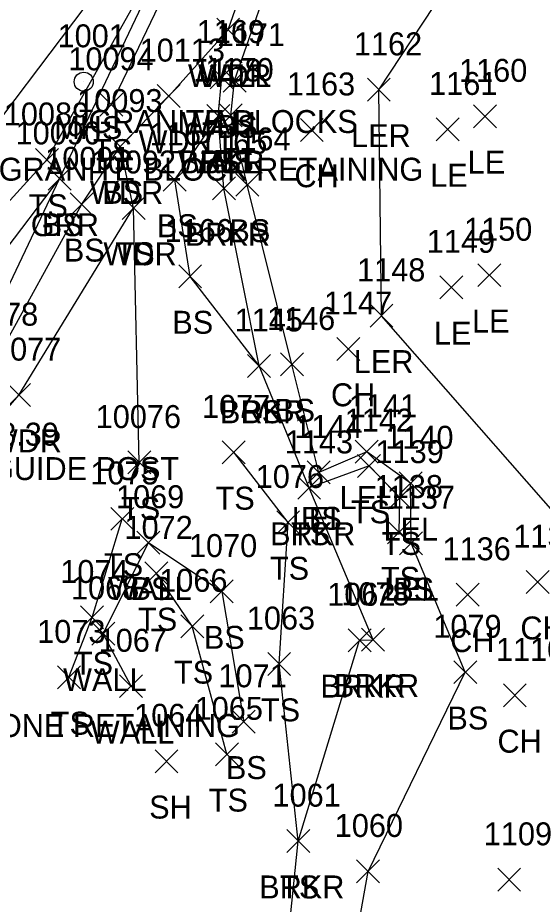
# Model space of a CAD drawing. Extents: x 1651685 to 1653558, y 889533 to 891085.
# Drawn here: x 1652685.2 to 1652731, y 890137.3 to 890214.6 of the extents above; entities that cross this region are included whole.
import ezdxf

# ---------------------------------------------------------------- set-up
doc = ezdxf.new("R2010")
doc.units = 0
for name, color, linetype in [('C_C', 7, 'Continuous'), ('L_A', 7, 'Continuous'), ('L_C', 7, 'Continuous'), ('L_I', 7, 'Continuous'), ('L_TIC', 7, 'Continuous'), ('LARO', 7, 'Continuous'), ('LAWA', 7, 'Continuous'), ('LAWE', 7, 'Continuous'), ('LELB', 7, 'Continuous'), ('LW', 7, 'Continuous'), ('PET', 7, 'Continuous'), ('R_A', 7, 'Continuous'), ('R_I', 7, 'Continuous'), ('R_TIC', 7, 'Continuous'), ('RGR', 7, 'Continuous'), ('U_A', 7, 'Continuous'), ('U_I', 7, 'Continuous'), ('USMH', 7, 'Continuous')]:
    doc.layers.add(name, color=color, linetype=linetype)

msp = doc.modelspace()

# ---------------------------------------------------------------- linework, layer by layer
at = {"layer": 'L_TIC'}
for points in [[(1652702.573, 890212.567), (1652704.573, 890214.567)], [(1652704.573, 890212.567), (1652702.573, 890214.567)], [(1652702.573, 890212.567), (1652704.573, 890214.567)], [(1652704.573, 890212.567), (1652702.573, 890214.567)], [(1652702.011, 890208.412), (1652704.011, 890210.412)], [(1652704.011, 890208.412), (1652702.011, 890210.412)], [(1652703.13, 890208.141), (1652705.13, 890210.141)], [(1652705.13, 890208.141), (1652703.13, 890210.141)], [(1652715.703, 890207.338), (1652717.703, 890209.338)], [(1652717.703, 890207.338), (1652715.703, 890209.338)], [(1652697.388, 890206.793), (1652699.388, 890208.793)], [(1652699.388, 890206.793), (1652697.388, 890208.793)], [(1652692.386, 890206.032), (1652694.386, 890208.032)], [(1652694.386, 890206.032), (1652692.386, 890208.032)], [(1652701.705, 890205.049), (1652703.705, 890207.049)], [(1652703.705, 890205.049), (1652701.705, 890207.049)], [(1652701.705, 890205.049), (1652703.705, 890207.049)], [(1652703.705, 890205.049), (1652701.705, 890207.049)], [(1652701.705, 890205.049), (1652703.705, 890207.049)], [(1652703.705, 890205.049), (1652701.705, 890207.049)], [(1652702.806, 890205.099), (1652704.806, 890207.099)], [(1652704.806, 890205.099), (1652702.806, 890207.099)], [(1652724.956, 890205.026), (1652726.956, 890207.026)], [(1652726.956, 890205.026), (1652724.956, 890207.026)], [(1652709.863, 890203.842), (1652711.863, 890205.842)], [(1652711.863, 890203.842), (1652709.863, 890205.842)], [(1652721.694, 890203.887), (1652723.694, 890205.887)], [(1652723.694, 890203.887), (1652721.694, 890205.887)], [(1652693.159, 890202.394), (1652695.159, 890204.394)], [(1652695.159, 890202.394), (1652693.159, 890204.394)], [(1652693.159, 890202.394), (1652695.159, 890204.394)], [(1652695.159, 890202.394), (1652693.159, 890204.394)], [(1652686.771, 890201.227), (1652688.771, 890203.227)], [(1652688.771, 890201.227), (1652686.771, 890203.227)], [(1652687.877, 890199.577), (1652689.877, 890201.577)], [(1652689.877, 890199.577), (1652687.877, 890201.577)], [(1652697.914, 890199.485), (1652699.914, 890201.485)], [(1652699.914, 890199.485), (1652697.914, 890201.485)], [(1652702.203, 890198.74), (1652704.203, 890200.74)], [(1652704.203, 890198.74), (1652702.203, 890200.74)], [(1652704.235, 890199.05), (1652706.235, 890201.05)], [(1652706.235, 890199.05), (1652704.235, 890201.05)], [(1652689.804, 890197.36), (1652691.804, 890199.36)], [(1652691.804, 890197.36), (1652689.804, 890199.36)], [(1652694.334, 890197.043), (1652696.334, 890199.043)], [(1652696.334, 890197.043), (1652694.334, 890199.043)], [(1652694.334, 890197.043), (1652696.334, 890199.043)], [(1652696.334, 890197.043), (1652694.334, 890199.043)], [(1652699.258, 890191.069), (1652701.258, 890193.069)], [(1652701.258, 890191.069), (1652699.258, 890193.069)], [(1652725.342, 890191.177), (1652727.342, 890193.177)], [(1652727.342, 890191.177), (1652725.342, 890193.177)], [(1652722.016, 890190.124), (1652724.016, 890192.124)], [(1652724.016, 890190.124), (1652722.016, 890192.124)], [(1652715.936, 890187.64), (1652717.936, 890189.64)], [(1652717.936, 890187.64), (1652715.936, 890189.64)], [(1652713.044, 890184.75), (1652715.044, 890186.75)], [(1652715.044, 890184.75), (1652713.044, 890186.75)], [(1652705.265, 890183.27), (1652707.265, 890185.27)], [(1652707.265, 890183.27), (1652705.265, 890185.27)], [(1652705.265, 890183.27), (1652707.265, 890185.27)], [(1652707.265, 890183.27), (1652705.265, 890185.27)], [(1652708.134, 890183.396), (1652710.134, 890185.396)], [(1652710.134, 890183.396), (1652708.134, 890185.396)], [(1652684.338, 890180.728), (1652686.338, 890182.728)], [(1652686.338, 890180.728), (1652684.338, 890182.728)], [(1652703.06, 890175.736), (1652705.06, 890177.736)], [(1652705.06, 890175.736), (1652703.06, 890177.736)], [(1652714.646, 890175.788), (1652716.646, 890177.788)], [(1652716.646, 890175.788), (1652714.646, 890177.788)], [(1652694.826, 890174.851), (1652696.826, 890176.851)], [(1652696.826, 890174.851), (1652694.826, 890176.851)], [(1652710.469, 890173.982), (1652712.469, 890175.982)], [(1652712.469, 890173.982), (1652710.469, 890175.982)], [(1652710.469, 890173.982), (1652712.469, 890175.982)], [(1652712.469, 890173.982), (1652710.469, 890175.982)], [(1652714.858, 890174.546), (1652716.858, 890176.546)], [(1652716.858, 890174.546), (1652714.858, 890176.546)], [(1652709.632, 890172.639), (1652711.632, 890174.639)], [(1652711.632, 890172.639), (1652709.632, 890174.639)], [(1652709.632, 890172.639), (1652711.632, 890174.639)], [(1652711.632, 890172.639), (1652709.632, 890174.639)], [(1652718.474, 890173.046), (1652720.474, 890175.046)], [(1652720.474, 890173.046), (1652718.474, 890175.046)], [(1652717.549, 890171.791), (1652719.549, 890173.791)], [(1652719.549, 890171.791), (1652717.549, 890173.791)], [(1652693.338, 890169.936), (1652695.338, 890171.936)], [(1652695.338, 890169.936), (1652693.338, 890171.936)], [(1652707.8, 890169.627), (1652709.8, 890171.627)], [(1652709.8, 890169.627), (1652707.8, 890171.627)], [(1652717.468, 890168.754), (1652719.468, 890170.754)], [(1652719.468, 890168.754), (1652717.468, 890170.754)], [(1652695.621, 890167.866), (1652697.621, 890169.866)], [(1652697.621, 890167.866), (1652695.621, 890169.866)], [(1652695.621, 890167.866), (1652697.621, 890169.866)], [(1652697.621, 890167.866), (1652695.621, 890169.866)], [(1652718.518, 890167.815), (1652720.518, 890169.815)], [(1652720.518, 890167.815), (1652718.518, 890169.815)], [(1652718.518, 890167.815), (1652720.518, 890169.815)], [(1652720.518, 890167.815), (1652718.518, 890169.815)], [(1652696.306, 890165.191), (1652698.306, 890167.191)], [(1652698.306, 890165.191), (1652696.306, 890167.191)], [(1652729.555, 890164.427), (1652731.555, 890166.427)], [(1652731.555, 890164.427), (1652729.555, 890166.427)], [(1652702.01, 890163.608), (1652704.01, 890165.608)], [(1652704.01, 890163.608), (1652702.01, 890165.608)], [(1652723.438, 890163.325), (1652725.438, 890165.325)], [(1652725.438, 890163.325), (1652723.438, 890165.325)], [(1652690.707, 890161.348), (1652692.707, 890163.348)], [(1652692.707, 890161.348), (1652690.707, 890163.348)], [(1652699.436, 890160.577), (1652701.436, 890162.577)], [(1652701.436, 890160.577), (1652699.436, 890162.577)], [(1652691.688, 890159.919), (1652693.688, 890161.919)], [(1652693.688, 890159.919), (1652691.688, 890161.919)], [(1652714.024, 890159.357), (1652716.024, 890161.357)], [(1652716.024, 890159.357), (1652714.024, 890161.357)], [(1652715.197, 890159.404), (1652717.197, 890161.404)], [(1652717.197, 890159.404), (1652715.197, 890161.404)], [(1652707.018, 890157.286), (1652709.018, 890159.286)], [(1652709.018, 890157.286), (1652707.018, 890159.286)], [(1652688.697, 890156.124), (1652690.697, 890158.124)], [(1652690.697, 890156.124), (1652688.697, 890158.124)], [(1652723.235, 890156.573), (1652725.235, 890158.573)], [(1652725.235, 890156.573), (1652723.235, 890158.573)], [(1652694.103, 890155.352), (1652696.103, 890157.352)], [(1652696.103, 890155.352), (1652694.103, 890157.352)], [(1652727.558, 890154.558), (1652729.558, 890156.558)], [(1652729.558, 890154.558), (1652727.558, 890156.558)], [(1652703.931, 890152.255), (1652705.931, 890154.255)], [(1652705.931, 890152.255), (1652703.931, 890154.255)], [(1652702.469, 890149.421), (1652704.469, 890151.421)], [(1652704.469, 890149.421), (1652702.469, 890151.421)], [(1652697.195, 890148.813), (1652699.195, 890150.813)], [(1652699.195, 890148.813), (1652697.195, 890150.813)], [(1652708.687, 890141.851), (1652710.687, 890143.851)], [(1652710.687, 890141.851), (1652708.687, 890143.851)], [(1652708.687, 890141.851), (1652710.687, 890143.851)], [(1652710.687, 890141.851), (1652708.687, 890143.851)], [(1652714.766, 890139.208), (1652716.766, 890141.208)], [(1652716.766, 890139.208), (1652714.766, 890141.208)], [(1652727.067, 890138.481), (1652729.067, 890140.481)], [(1652729.067, 890138.481), (1652727.067, 890140.481)]]:
    msp.add_lwpolyline(points, dxfattribs=at)
at = {"layer": 'LARO'}
for points in [[(1652741.291, 890109.75), (1652743.69, 890134.843), (1652747.37, 890143.521), (1652742.713, 890157.365), (1652736.668, 890166.137), (1652716.936, 890188.64), (1652716.703, 890208.338), (1652726.418, 890223.049), (1652732.201, 890228.998)], [(1652719.518, 890168.815), (1652719.474, 890174.046), (1652715.646, 890176.788), (1652711.469, 890174.982)]]:
    msp.add_lwpolyline(points, dxfattribs=at)
at = {"layer": 'LAWA'}
msp.add_lwpolyline([(1652680.109, 890167.148), (1652679.001, 890174.399), (1652685.338, 890181.728), (1652695.334, 890198.043), (1652694.159, 890203.394), (1652698.388, 890207.793), (1652703.573, 890213.567)], dxfattribs=at)
at = {"layer": 'LAWE'}
msp.add_lwpolyline([(1652706.559, 890112.43), (1652709.687, 890142.851), (1652715.024, 890160.357), (1652716.197, 890160.404), (1652710.632, 890173.639), (1652706.265, 890184.27), (1652703.203, 890199.74), (1652702.705, 890206.049)], dxfattribs=at)
at = {"layer": 'LELB'}
for points in [[(1652059.958, 889769.148), (1652077.097, 889776.338), (1652118.687, 889793.555), (1652148.832, 889805.136), (1652195.565, 889824.702), (1652235.22, 889839.021), (1652273.168, 889851.707), (1652312.186, 889868.505), (1652346.463, 889887.35), (1652384.438, 889904.888), (1652418.627, 889927.641), (1652449.257, 889948.785), (1652484.179, 889973.177), (1652505.899, 889994.659), (1652536.895, 890025.511), (1652566.282, 890055.689), (1652594.629, 890083.579), (1652622.175, 890122.044), (1652650.057, 890154.468), (1652669.869, 890181.835), (1652676.091, 890189.411), (1652687.771, 890202.227), (1652700.091, 890224.174)], [(1652693.386, 890207.032), (1652701.322, 890223.637)], [(1652711.469, 890174.982), (1652709.134, 890184.396), (1652705.235, 890200.05), (1652703.806, 890206.099), (1652704.13, 890209.141), (1652708.172, 890220.743), (1652707.273, 890221.555)], [(1652706.265, 890184.27), (1652700.258, 890192.069), (1652698.914, 890200.485), (1652702.705, 890206.049)], [(1652510.075, 889988.608), (1652541.256, 890021.657), (1652570.449, 890051.196), (1652599.255, 890080.662), (1652627.515, 890117.732), (1652652.742, 890152.479), (1652673.773, 890178.689), (1652683.325, 890184.776), (1652690.804, 890198.36), (1652694.159, 890203.394)], [(1652425.64, 889918.847), (1652456.726, 889936.262), (1652476.981, 889952.39), (1652484.779, 889967.501), (1652507.93, 889991.53), (1652539.732, 890022.766), (1652568.751, 890053.154), (1652596.439, 890082.379), (1652624.715, 890120.116), (1652650.778, 890153.905), (1652671.989, 890180.33), (1652678.44, 890186.862), (1652688.877, 890200.577)], [(1652695.826, 890175.851), (1652695.334, 890198.043)], [(1652709.687, 890142.851), (1652708.018, 890158.286), (1652708.8, 890170.627), (1652704.06, 890176.736)], [(1652718.468, 890169.754), (1652718.549, 890172.791), (1652715.858, 890175.546), (1652710.632, 890173.639)], [(1652689.697, 890157.124), (1652691.707, 890162.348), (1652694.338, 890170.936)], [(1652696.621, 890168.866), (1652703.01, 890164.608), (1652704.931, 890153.255)], [(1652710.525, 890110.796), (1652715.766, 890140.208), (1652724.235, 890157.573), (1652719.518, 890168.815)], [(1652703.469, 890150.421), (1652700.436, 890161.577), (1652697.306, 890166.191)]]:
    msp.add_lwpolyline(points, dxfattribs=at)
at = {"layer": 'LW'}
for points in [[(1652703.573, 890213.567), (1652706.281, 890221.305)], [(1652702.705, 890206.049), (1652703.011, 890209.412)], [(1652695.103, 890156.352), (1652692.688, 890160.919), (1652696.621, 890168.866)]]:
    msp.add_lwpolyline(points, dxfattribs=at)
at = {"layer": 'PET'}
msp.add_lwpolyline([(1652310.071, 889873.858), (1652345.018, 889890.876), (1652381.133, 889910.269), (1652416.225, 889931.732), (1652447.247, 889952.285), (1652474.07, 889972.993), (1652503.702, 889997.944), (1652534.457, 890027.787), (1652563.385, 890057.924), (1652590.108, 890087.923), (1652620.326, 890123.876), (1652646.593, 890156.843), (1652667.225, 890184.01), (1652673.844, 890192.76), (1652698.186, 890224.989), (1652707.052, 890238.801), (1652697.139, 890249.857), (1652688.173, 890260.372)], dxfattribs=at)
at = {"layer": 'R_TIC'}
for points in [[(1652687.877, 890199.577), (1652689.877, 890201.577)], [(1652689.877, 890199.577), (1652687.877, 890201.577)]]:
    msp.add_lwpolyline(points, dxfattribs=at)
at = {"layer": 'RGR'}
msp.add_lwpolyline([(1652681.549, 890185.195), (1652688.877, 890200.577), (1652700.091, 890224.174), (1652707.601, 890236.977), (1652707.742, 890237.28)], dxfattribs=at)
at = {"layer": 'USMH'}
for p, q in [((1652690.983, 890209.037), (1652690.983, 890209.037)), ((1652691.817, 890209.037), (1652691.817, 890209.037))]:
    msp.add_line(p, q, dxfattribs=at)
msp.add_circle((1652690.983, 890209.037), 0.833, dxfattribs=at)

# ---------------------------------------------------------------- texts
at = {"layer": 'C_C'}
for s, p in [('TIE= 18.39', (1652675.659, 890177.318)), ('NAIL ON TOP OF GUIDE POST', (1652660.667, 890174.318))]:
    msp.add_text(s, height=2, dxfattribs=at).set_placement(p)
at = {"layer": 'L_A'}
for s, p in [('WALL', (1652700.062, 890208.567)), ('WDR', (1652700.936, 890208.567)), ('WALL', (1652699.499, 890204.412)), ('BS', (1652702.571, 890204.141)), ('LER', (1652714.286, 890203.338)), ('WDR', (1652695.75, 890202.793)), ('TS', (1652691.796, 890202.032)), ('WALL', (1652699.193, 890201.049)), ('BRKR', (1652699.295, 890201.049)), ('BS', (1652701.146, 890201.049)), ('BS', (1652702.247, 890201.099)), ('LE', (1652724.444, 890201.026)), ('CH', (1652709.352, 890199.842)), ('LE', (1652721.182, 890199.887)), ('WDR', (1652691.521, 890198.394)), ('BS', (1652692.6, 890198.394)), ('TS', (1652686.181, 890197.227)), ('BS', (1652687.318, 890195.577)), ('BS', (1652697.355, 890195.485)), ('BRKR', (1652699.793, 890194.74)), ('BS', (1652703.676, 890195.05)), ('BS', (1652689.245, 890193.36)), ('WDR', (1652692.696, 890193.043)), ('TS', (1652693.744, 890193.043)), ('BS', (1652698.699, 890187.069)), ('LE', (1652724.83, 890187.177)), ('LE', (1652721.505, 890186.124)), ('LER', (1652714.519, 890183.64)), ('CH', (1652712.532, 890180.75)), ('BRKR', (1652702.855, 890179.27)), ('BS', (1652704.706, 890179.27)), ('BS', (1652707.575, 890179.396)), ('WDR', (1652682.7, 890176.728)), ('TS', (1652702.469, 890171.736)), ('LEL', (1652713.284, 890171.788)), ('TS', (1652694.236, 890170.851)), ('LEL', (1652709.107, 890169.982)), ('BS', (1652709.91, 890169.982)), ('TS', (1652714.267, 890170.546)), ('BRKR', (1652707.223, 890168.639)), ('TS', (1652709.042, 890168.639)), ('LEL', (1652717.112, 890169.046)), ('TS', (1652716.958, 890167.791)), ('TS', (1652692.747, 890165.936)), ('TS', (1652707.209, 890165.627)), ('TS', (1652716.877, 890164.754)), ('WALL', (1652693.109, 890163.866)), ('BS', (1652695.062, 890163.866)), ('LEL', (1652717.156, 890163.815)), ('BS', (1652717.959, 890163.815)), ('TS', (1652695.715, 890161.191)), ('CH', (1652729.043, 890160.427)), ('BS', (1652701.451, 890159.608)), ('CH', (1652722.926, 890159.325)), ('TS', (1652690.116, 890157.348)), ('TS', (1652698.845, 890156.577)), ('WALL', (1652689.177, 890155.919)), ('BRKR', (1652711.614, 890155.357)), ('BRKR', (1652712.788, 890155.404)), ('TS', (1652706.427, 890153.286)), ('BS', (1652722.676, 890152.573)), ('TS', (1652688.106, 890152.124)), ('WALL', (1652691.591, 890151.352)), ('CH', (1652727.046, 890150.558)), ('BS', (1652703.372, 890148.255)), ('TS', (1652701.878, 890145.421)), ('SH', (1652696.683, 890144.813)), ('BRKR', (1652706.278, 890137.851)), ('TS', (1652708.096, 890137.851))]:
    msp.add_text(s, height=2, dxfattribs=at).set_placement(p)
at = {"layer": 'L_C'}
for s, p in [('GRANITE BLOCKS', (1652691.385, 890204.567)), ('GRANITE BLOCK RETAINING', (1652683.57, 890200.412)), ('STONE RETAINING', (1652680.083, 890151.919))]:
    msp.add_text(s, height=2, dxfattribs=at).set_placement(p)
at = {"layer": 'L_I'}
for s, p in [('1169', (1652700.83, 890212.412)), ('1171', (1652702.571, 890212.141)), ('1162', (1652714.53, 890211.338)), ('10113', (1652695.853, 890210.793)), ('10094', (1652689.639, 890210.032)), ('1168', (1652700.532, 890209.049)), ('1168', (1652700.532, 890209.049)), ('1168', (1652700.532, 890209.049)), ('1170', (1652701.594, 890209.099)), ('1160', (1652723.696, 890209.026)), ('1163', (1652708.69, 890207.842)), ('1161', (1652721.087, 890207.887)), ('10093', (1652690.411, 890206.394)), ('10093', (1652690.411, 890206.394)), ('10089', (1652684.015, 890205.227)), ('10090', (1652685.042, 890203.577)), ('1167', (1652696.741, 890203.485)), ('1165', (1652701.03, 890202.74)), ('1164', (1652703.062, 890203.05)), ('10091', (1652687.623, 890201.36)), ('10092', (1652691.586, 890201.043)), ('10092', (1652691.586, 890201.043)), ('1166', (1652698.03, 890195.069)), ('1150', (1652724.13, 890195.177)), ('1149', (1652720.883, 890194.124)), ('1148', (1652714.81, 890191.64)), ('1147', (1652711.918, 890188.75)), ('10078', (1652679.577, 890187.776)), ('1145', (1652704.139, 890187.27)), ('1145', (1652704.139, 890187.27)), ('1146', (1652706.953, 890187.396)), ('10077', (1652681.59, 890184.728)), ('1077', (1652701.288, 890179.736)), ('1141', (1652714.088, 890179.788)), ('10076', (1652692.024, 890178.851)), ('1142', (1652713.732, 890178.546)), ('1144', (1652709.343, 890177.982)), ('1144', (1652709.343, 890177.982)), ('1140', (1652717.262, 890177.046)), ('1143', (1652708.507, 890176.639)), ('1143', (1652708.507, 890176.639)), ('1139', (1652716.415, 890175.791)), ('1075', (1652691.566, 890173.936)), ('1076', (1652705.973, 890173.627)), ('1138', (1652716.342, 890172.754)), ('1069', (1652693.794, 890171.866)), ('1069', (1652693.794, 890171.866)), ('1137', (1652717.393, 890171.815)), ('1137', (1652717.393, 890171.815)), ('1072', (1652694.534, 890169.191)), ('1135', (1652728.43, 890168.427)), ('1070', (1652700.152, 890167.608)), ('1136', (1652722.257, 890167.325)), ('1074', (1652688.935, 890165.348)), ('1066', (1652697.562, 890164.577)), ('1068', (1652689.87, 890163.919)), ('1062', (1652712.205, 890163.357)), ('1078', (1652713.426, 890163.404)), ('1063', (1652705.199, 890161.286)), ('1073', (1652686.925, 890160.124)), ('1079', (1652721.456, 890160.573)), ('1067', (1652692.284, 890159.352)), ('1110', (1652726.913, 890158.558)), ('1071', (1652702.726, 890156.255)), ('1065', (1652700.65, 890153.421)), ('1064', (1652695.376, 890152.813)), ('1061', (1652707.435, 890145.851)), ('1061', (1652707.435, 890145.851)), ('1060', (1652712.861, 890143.208)), ('1109', (1652725.855, 890142.481))]:
    msp.add_text(s, height=2, dxfattribs=at).set_placement(p)
at = {"layer": 'R_A'}
msp.add_text('GRR', height=2, dxfattribs=at).set_placement((1652686.365, 890195.577))
at = {"layer": 'R_I'}
msp.add_text('10090', height=2, dxfattribs=at).set_placement((1652685.042, 890203.577))
at = {"layer": 'U_A'}
msp.add_text('MHS', height=2, dxfattribs=at).set_placement((1652688.401, 890204.037))
at = {"layer": 'U_I'}
msp.add_text('1001', height=2, dxfattribs=at).set_placement((1652688.7, 890212.037))

doc.saveas('drawing.dxf')
